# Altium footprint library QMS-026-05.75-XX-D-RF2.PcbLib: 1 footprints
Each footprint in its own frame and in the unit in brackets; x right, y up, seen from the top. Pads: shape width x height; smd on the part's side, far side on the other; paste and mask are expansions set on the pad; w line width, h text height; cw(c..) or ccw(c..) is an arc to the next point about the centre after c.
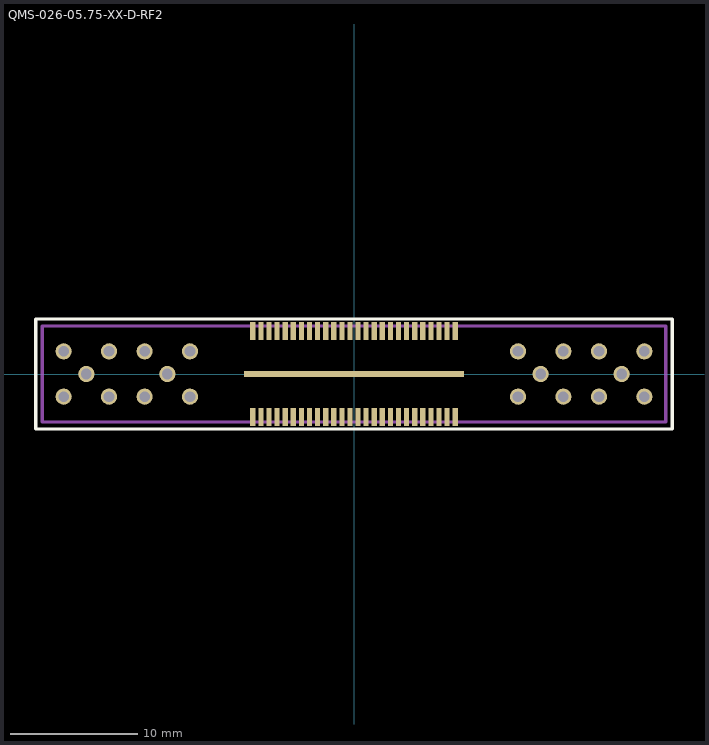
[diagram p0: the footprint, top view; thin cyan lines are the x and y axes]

## QMS-026-05.75-XX-D-RF2 [mil]
pads (73):
  rect 16x55 smd mask+2: 1(-312.5,-132.5) 2(-312.5,132.5) 3(-287.5,-132.5) 4(-287.5,132.5) 5(-262.5,-132.5) 6(-262.5,132.5) 7(-237.5,-132.5) 8(-237.5,132.5) 9(-212.5,-132.5) 10(-212.5,132.5) 11(-187.5,-132.5) 12(-187.5,132.5) 13(-162.5,-132.5) 14(-162.5,132.5) 15(-137.5,-132.5) 16(-137.5,132.5) 17(-112.5,-132.5) 18(-112.5,132.5) 19(-87.5,-132.5) 20(-87.5,132.5) 21(-62.5,-132.5) 22(-62.5,132.5) 23(-37.5,-132.5) 24(-37.5,132.5) 25(-12.5,-132.5) 26(-12.5,132.5) 27(12.5,-132.5) 28(12.5,132.5) 29(37.5,-132.5) 30(37.5,132.5) 31(62.5,-132.5) 32(62.5,132.5) 33(87.5,-132.5) 34(87.5,132.5) 35(112.5,-132.5) 36(112.5,132.5) 37(137.5,-132.5) 38(137.5,132.5) 39(162.5,-132.5) 40(162.5,132.5) 41(187.5,-132.5) 42(187.5,132.5) 43(212.5,-132.5) 44(212.5,132.5) 45(237.5,-132.5) 46(237.5,132.5) 47(262.5,-132.5) 48(262.5,132.5) 49(287.5,-132.5) 50(287.5,132.5) 51(312.5,-132.5) 52(312.5,132.5)
  rect 680x20 smd mask+2: 53(0,0)
  round 50 hole 33 mask+3: RF01-1(-826.5,0) RF01-2(-896.5,70) RF01-3(-756.5,70) RF01-4(-896.5,-70) RF01-5(-756.5,-70) RF02-1(-576.5,0) RF02-2(-646.5,70) RF02-3(-506.5,70) RF02-4(-646.5,-70) RF02-5(-506.5,-70) RF03-1(576.5,0) RF03-2(506.5,70) RF03-3(646.5,70) RF03-4(506.5,-70) RF03-5(646.5,-70) RF04-1(826.5,0) RF04-2(756.5,70) RF04-3(896.5,70) RF04-4(756.5,-70) RF04-5(896.5,-70)
Top Overlay:
  lines w10: -982.5,-170 982.5,-170 982.5,170 -982.5,170 -982.5,-170
Mechanical 1:
  lines w10: -962.5,-148 962.5,-148 962.5,148 -962.5,148 -962.5,-148
  text "J1" at -19.57,-20 h30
